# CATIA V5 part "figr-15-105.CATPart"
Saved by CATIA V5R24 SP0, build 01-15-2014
Part number: Part1
Bounding box of the stored display mesh (mm): x -66.07 to 66.07, y -35.456 to 35.456, z -8 to 1
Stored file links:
  D:\KAVITA\CATIA V5-6R2014 Project_ Kavita\CATIA V5-6R2014_partfiles\Partfiles\c15_catia_v5-6r2014_prt\figr-15-105.CATPart
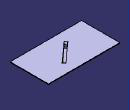
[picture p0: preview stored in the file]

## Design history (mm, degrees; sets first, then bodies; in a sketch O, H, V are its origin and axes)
SheetMetalParameters1: Thickness 1, BendRadius 5, KFactor 0.5 {= log(min(100,max(20*SheetMetalParameters1.BendRadius,SheetMetalParameters1.Thickness)/SheetMetalParameters1.Thickness))/log(100)/2}, ReliefRadialLength 1, ReliefAxialLength 2, MinimumBendRadius 0
Body1 (main body)
  Sketch1 on xy-plane, origin (0, 0, 0), H (1, 0, 0), V (0, 1, 0)
    line L1 (66.07, 35.4565) -> (66.07, -35.4565)
    line L2 (66.07, -35.4565) -> (-66.07, -35.4565)
    line L3 (-66.07, -35.4565) -> (-66.07, 35.4565)
    line L4 (-66.07, 35.4565) -> (66.07, 35.4565)
    vertical: L1 V, L3 V
    horizontal: L2 H, L4 H
    equidistance: L1 L3 O, L2 L4 O
  Wall1: Thickness 1, Profile Sketch1
  Sketch2 on face of Wall1, origin (0, 0, 1), H (1, 0, 0), V (0, 1, 0)
    point P1 (0, 0)
    coincidence: P1 O
  Sketch3 on face of Wall1, origin (0, 0, 1), H (1, 0, 0), V (0, 1, 0)
    point P1 (0, 0)
    reference projected point E1 (0, 0) from Sketch2.P1
    coincidence: E1 P1
  d_Stamp1: Stamp_FilletRadius 2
